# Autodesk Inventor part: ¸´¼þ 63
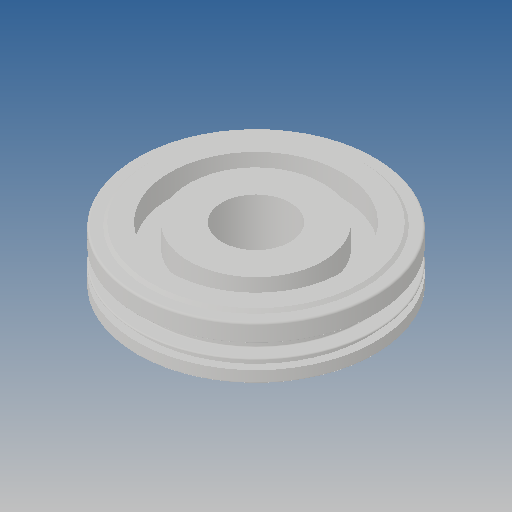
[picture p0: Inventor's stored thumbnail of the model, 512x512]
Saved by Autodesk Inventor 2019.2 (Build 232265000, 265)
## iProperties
Created: 2013-07
Part Number: ¸´¼þ 63
Material: Ogólny
Document SubType Name: Modeling
Designer: CADENGINEERING4
Density: 1 g/cm^3
Appearance: Domyślna
Author: CADENGINEERING4
Revision Number: ÈÎºÎ
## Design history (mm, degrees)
feature "Ðý×ª1"
node "Bryła1"
